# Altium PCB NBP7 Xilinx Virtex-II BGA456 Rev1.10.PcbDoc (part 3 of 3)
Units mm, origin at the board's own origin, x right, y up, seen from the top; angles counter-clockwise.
Board outline 69 x 80.99 mm, 6 copper layers (Top Layer, MidLayer1, InternalPlane1, InternalPlane2, MidLayer2, Bottom Layer); 101 components, 273 nets, 963 pads, 545 vias.
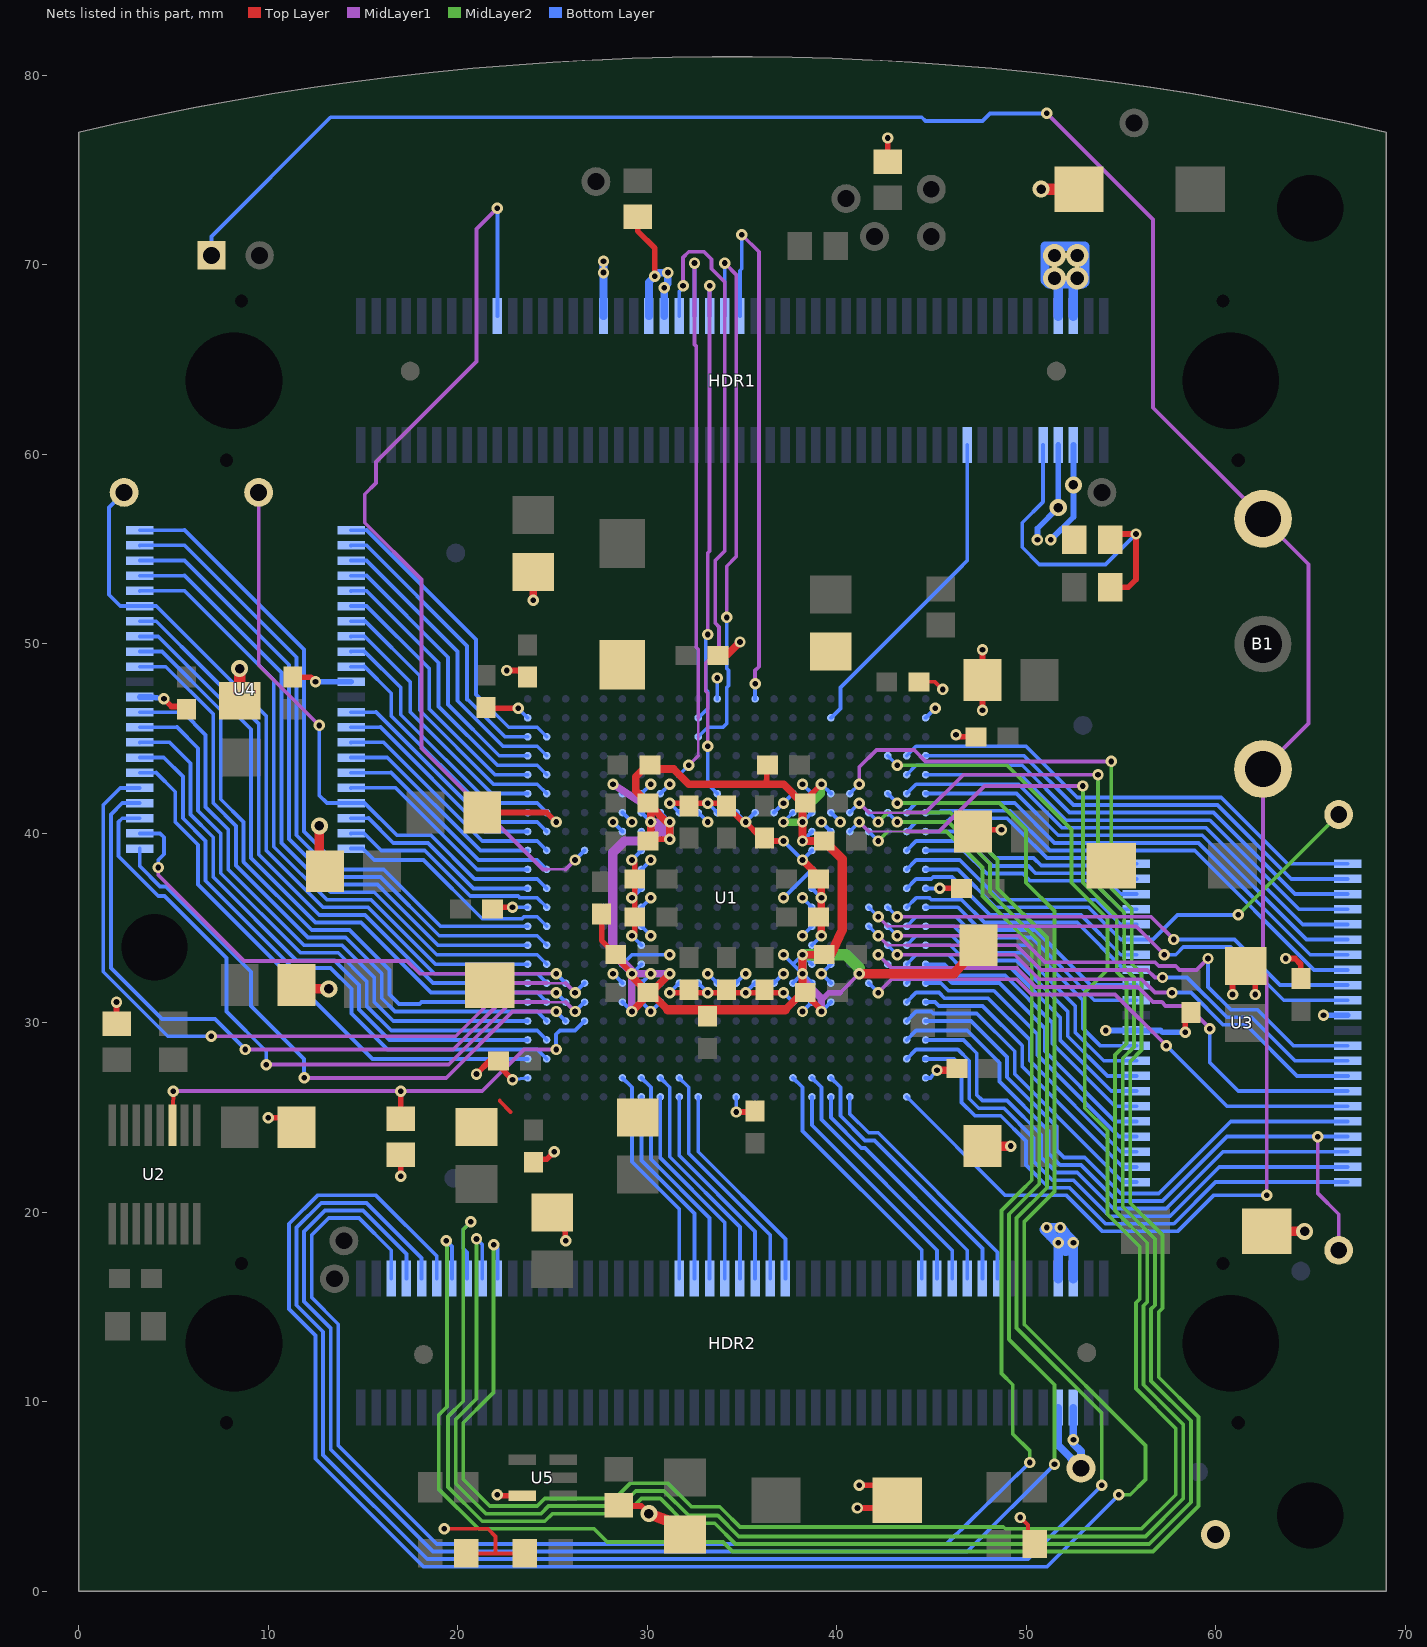
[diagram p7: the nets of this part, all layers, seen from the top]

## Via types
v1: diameter 0.6, hole 0.3, Top Layer to Bottom Layer, tented bottom, 520 vias
v2: diameter 0.9, hole 0.5, Top Layer to Bottom Layer, 17 vias
v3: diameter 1.2, hole 0.7, Top Layer to Bottom Layer, 8 vias

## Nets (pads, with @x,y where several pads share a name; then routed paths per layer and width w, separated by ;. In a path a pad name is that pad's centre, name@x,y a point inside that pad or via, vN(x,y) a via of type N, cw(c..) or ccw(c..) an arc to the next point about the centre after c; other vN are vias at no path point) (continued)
SP10: HDR2.86 U1.A18 | length 13.1
  Bottom Layer w0.2: U1.A18@40.7,26.1 40.7,25.2 41.7,24.2 42.2,24.2 48.5,17.9 HDR2.86@48.5,16.5
SP11: HDR2.84 U1.B17 | length 14.2
  Bottom Layer w0.2: U1.B17@39.7,27.1 40.2,26.6 40.2,25.1 41.5,23.8 42,23.8 47.7,18.1 HDR2.84@47.7,16.5
SP12: HDR2.82 U1.A17 | length 12.7
  Bottom Layer w0.2: U1.A17@39.7,26.1 39.7,25 41.3,23.4 41.5,23.4 46.9,18 HDR2.82@46.9,16.5
SP13: HDR2.80 U1.B16 | length 13.7
  Bottom Layer w0.2: U1.B16@38.7,27.1 39.2,26.6 39.2,24.9 46.1,18 HDR2.80@46.1,16.5
SP14: HDR2.78 U1.A16 | length 12.3
  Bottom Layer w0.2: U1.A16@38.7,26.1 38.7,24.6 45.3,18 HDR2.78@45.3,16.5
SP15: HDR2.76 U1.B15 | length 13.4
  Bottom Layer w0.2: U1.B15@37.7,27.1 38.2,26.6 38.2,24.3 44.5,18 HDR2.76@44.5,16.5
SPI_CLK: HDR1.46 U1.V9 | length 30.3
  MidLayer1 w0.127: 32.7,44.1 32.7,46.1
  MidLayer1 w0.2: v1(32.2,43.6) 32.7,44.1 ; v1(32.5,70.1) 32.5,65.8 32.6,65.7 32.6,49.8 32.7,49.7 32.7,46.1
  Bottom Layer w0.2: U1.V9@31.7,43.1 v1(32.2,43.6) ; HDR1.46@32.5,67.3 v1(32.5,70.1)
SPI_DIN: HDR1.44 U1.U11 | length 34.3
  MidLayer1 w0.2: v1(31.9,68.9) 31.9,70.4 32.2,70.7 33,70.7 33.4,70.3 33.4,69.8 34.1,69.1 34.1,54.9 33.6,54.4 33.6,51.1 33.8,50.9 33.8,49.7 33.1,49 33.1,47.5 33.2,47.4 v1(33.2,44.6)
  Bottom Layer w0.2: HDR1.44@31.7,67.3 31.7,68.6 31.9,68.8 v1(31.9,68.9) ; v1(33.2,44.6) 33.2,42.6 U1.U11@33.7,42.1
SPI_DOUT: HDR1.50 U1.Y10 | length 29.8
  MidLayer1 w0.2: v1(34.2,51.4) 34.2,54.1 34.7,54.6 34.7,69.5 v1@34.15,70.05 ; v1(34.1,70.1) v1@34.15,70.05 ; v1(34.1,70.1) 34.2,70.1 v1@34.15,70.05 ; v1(34.1,70.1) 34.1,70 v1@34.15,70.05
  Bottom Layer w0.2: U1.Y10@32.7,45.1 33.2,45.6 34,45.6 34.2,45.8 34.2,47.7 34.3,47.8 34.3,48.6 34.2,48.7 v1(34.2,51.4) ; HDR1.50@34.1,67.3 v1(34.1,70.1)
SPI_MODE: HDR1.52 U1.AB13 | length 29.4
  MidLayer1 w0.2: v1@34.9,71.6 34.95,71.65 v1(35,71.6) 35.9,70.7 35.9,48.8 35.7,48.6 v1(35.7,47.9)
  Bottom Layer w0.2: HDR1.52@34.9,67.3 34.9,69.7 35,69.8 v1(35,71.6) ; U1.AB13@35.7,47.1 v1(35.7,47.9)
SPI_SEL: HDR1.48 U1.AA10 | length 24.8
  MidLayer1 w0.2: v1(33.2,50.5) 33.2,54.8 33.3,54.9 v1(33.3,68.9)
  Bottom Layer w0.2: U1.AA10@32.7,46.1 33.2,46.6 33.2,47.5 33.1,47.6 33.1,50.5 v1(33.2,50.5) ; HDR1.48@33.3,67.3 v1(33.3,68.9)
SRAM0_A0: U1.G21 U3.5 | length 16.3
  Bottom Layer w0.2: U1.G21@43.7,32.1 44.2,32.6 45.6,32.6 46.1,32.1 48.6,32.1 51,29.7 51,28.5 54.7,24.8 U3.5@55.825,24.8
SRAM0_A1: U1.G22 U3.4 | length 15.1
  Bottom Layer w0.2: U1.G22@44.7,32.1 45.5,32.1 45.9,31.7 48.3,31.7 50.6,29.4 50.6,28.3 54.9,24 U3.4@55.825,24
SRAM0_A2: U1.F21 U3.3 | length 16.5
  Bottom Layer w0.2: U1.F21@43.7,31.1 44.2,31.6 45.4,31.6 45.7,31.3 48,31.3 50.2,29.1 50.2,28 55,23.2 U3.3@55.825,23.2
SRAM0_A3: U1.F22 U3.2 | length 15.4
  Bottom Layer w0.2: U1.F22@44.7,31.1 45.2,31.1 45.4,30.9 47.7,30.9 49.8,28.8 49.8,27.7 55.1,22.4 U3.2@55.825,22.4
SRAM0_A4: U1.E21 U3.1 | length 16.8
  Bottom Layer w0.2: U1.E21@43.7,30.1 44.2,30.6 45,30.6 45.1,30.5 47.4,30.5 49.4,28.5 49.4,27.3 55.1,21.6 U3.1@55.825,21.6
SRAM0_A5: U1.C22 U3.44 | length 28.7
  Bottom Layer w0.2: U1.C22@44.6,28.1 U1.C22@44.7,28.1 46.2,28.1 46.6,27.7 46.6,25.8 47.3,25.1 48.669,25.1 50,23.769 50,22.5 51.2,21.3 52.3,21.3 54.2,19.4 57.8,19.4 60,21.6 U3.44@66.975,21.6
SRAM0_A6: U1.C21 U3.43 | length 30.1
  Bottom Layer w0.2: U1.C21@43.7,28.1 44.2,28.6 46.4,28.6 47,28 47,26 47.5,25.5 48.834,25.5 50.4,23.934 50.4,22.7 51.4,21.7 52.5,21.7 54.4,19.8 57.6,19.8 60.2,22.4 U3.43@66.975,22.4
SRAM0_A7: U1.D22 U3.42 | length 29.2
  Bottom Layer w0.2: U1.D22@44.7,29.1 46.7,29.1 47.4,28.4 47.4,26.2 47.7,25.9 49,25.9 50.8,24.1 50.8,22.9 51.6,22.1 52.7,22.1 54.6,20.2 57.4,20.2 60.4,23.2 U3.42@66.975,23.2
SRAM0_A8: U1.N21 U3.18 | length 13.7
  Bottom Layer w0.2: U1.N21@43.7,38.1 44.2,38.6 46.5,38.6 48.6,36.5 53.7,36.5 55,35.2 U3.18@55.825,35.2
SRAM0_A9: U1.U21 U3.27 | length 26.5
  Bottom Layer w0.2: U1.U21@43.7,42.1 44.2,42.6 49.6,42.6 51.9,40.3 59.5,40.3 64.6,35.2 U3.27@66.975,35.2
SRAM0_A10: U1.V22 U3.26 | length 25.2
  Bottom Layer w0.2: U1.V22@44.7,43.1 49.7,43.1 52.1,40.7 59.7,40.7 64.4,36 U3.26@66.975,36
SRAM0_A11: U1.V21 U3.25 | length 26.3
  Bottom Layer w0.2: U1.V21@43.7,43.1 44.2,43.6 49.8,43.6 52.3,41.1 59.9,41.1 64.2,36.8 U3.25@66.975,36.8
SRAM0_A12: U1.W22 U3.24 | length 25
  Bottom Layer w0.2: U1.W22@44.7,44.1 49.9,44.1 52.5,41.5 60.1,41.5 64,37.6 U3.24@66.975,37.6
SRAM0_A13: U1.W21 U3.23 | length 26.1
  Bottom Layer w0.2: U1.W21@43.7,44.1 44.2,44.6 50,44.6 52.7,41.9 60.3,41.9 63.8,38.4 U3.23@66.975,38.4
SRAM0_A14: U1.R21 U3.22 | length 13.4
  Bottom Layer w0.2: U1.R21@43.7,40.1 44.2,40.6 ; 44.2,40.6 45.8,40.6 46,40.8 49,40.8 49.693,40.107 51.1,38.7 54.7,38.7 55,38.4 U3.22@55.825,38.4
SRAM0_A15: U1.R22 U3.21 | length 12.2
  Bottom Layer w0.2: U1.R22@44.7,40.1 47,40.1 48.4,38.7 50.4,38.7 50.8,38.3 54.3,38.3 55,37.6 U3.21@55.825,37.6
SRAM0_A16: U1.P21 U3.20 | length 13.5
  Bottom Layer w0.2: U1.P21@43.7,39.1 44.2,39.6 46.9,39.6 48.222,38.278 50.122,38.278 50.5,37.9 53.9,37.9 55,36.8 U3.20@55.825,36.8
SRAM0_A17: U1.P22 U3.19 | length 12.4
  Bottom Layer w0.2: U1.P22@44.7,39.1 46.7,39.1 47.922,37.878 49.822,37.878 50.2,37.5 53.5,37.5 55,36 U3.19@55.825,36
SRAM0_A18: U1.U22 U3.28 | length 25.5
  Bottom Layer w0.2: U1.U22@44.7,42.1 49.5,42.1 51.7,39.9 59.3,39.9 64.8,34.4 U3.28@66.975,34.4
SRAM0_D0: U1.H21 U3.7 | length 16
  Bottom Layer w0.2: U1.H21@43.7,33.1 44.2,33.6 45.9,33.6 46.6,32.9 49.2,32.9 51.8,30.3 51.8,29.1 54.5,26.4 U3.7@55.825,26.4
SRAM0_D1: U1.J22 U3.8 | length 14.7
  Bottom Layer w0.2: U1.J22@44.7,34.1 46,34.1 46.8,33.3 49.5,33.3 52.2,30.6 52.2,29.3 54.3,27.2 U3.8@55.825,27.2
SRAM0_D2: U1.J21 U3.9 | length 15.9
  Bottom Layer w0.2: U1.J21@43.7,34.1 44.2,34.6 46.1,34.6 47,33.7 49.8,33.7 52.6,30.9 52.6,29.5 54.1,28 U3.9@55.825,28
SRAM0_D3: U1.K22 U3.10 | length 14.6
  Bottom Layer w0.2: U1.K22@44.7,35.1 45.2,35.1 46.2,35.1 47.2,34.1 50.1,34.1 53,31.2 53,29.7 53.9,28.8 U3.10@55.825,28.8
SRAM0_D4: U1.K21 U3.13 | length 14.2
  Bottom Layer w0.2: U1.K21@43.7,35.1 44.2,35.6 46.3,35.6 47.4,34.5 50.3,34.5 53.6,31.2 U3.13@55.825,31.2
SRAM0_D5: U1.L22 U3.14 | length 12.8
  Bottom Layer w0.2: U1.L22@44.7,36.1 46.4,36.1 47.6,34.9 50.5,34.9 53.4,32 U3.14@55.825,32
SRAM0_D6: U1.L21 U3.15 | length 13.9
  Bottom Layer w0.2: U1.L21@43.7,36.1 44.2,36.6 44.9,36.6 45,36.5 46.6,36.5 47.8,35.3 52.7,35.3 55.2,32.8 U3.15@55.825,32.8
SRAM0_D7: U1.M21 U3.16 | length 14.1
  Bottom Layer w0.2: U1.M21@43.7,37.1 44.2,37.6 45,37.6 45.1,37.7 46.1,37.7 48.1,35.7 52.9,35.7 55,33.6 U3.16@55.825,33.6
SRAM0_D8: U1.T21 U3.29 | length 26.8
  Bottom Layer w0.2: U1.T21@43.7,41.1 44.2,41.6 49.4,41.6 51.5,39.5 59.1,39.5 65,33.6 U3.29@66.975,33.6
SRAM0_D9: U1.T22 U3.30 | length 25.8
  Bottom Layer w0.2: U1.T22@44.7,41.1 45.4,41.1 45.5,41.2 49.166,41.2 51.266,39.1 58.9,39.1 65.2,32.8 U3.30@66.975,32.8
SRAM0_D10: U1.L20 U3.31 | length 26
  MidLayer1 w0.2: v1(43.2,35.6) 56.6,35.6 v1(57.8,34.4)
  Bottom Layer w0.2: U1.L20@42.7,36.1 v1(43.2,35.6) ; v1(57.8,34.4) 61,34.4 63.4,32 U3.31@66.975,32
SRAM0_D11: U1.L19 U3.32 | length 27.6
  MidLayer1 w0.127: 42.7,35.1 43.7,35.1
  MidLayer1 w0.2: v1(42.2,35.6) 42.7,35.1 ; 43.7,35.1 55.8,35.1 v1(57.3,33.6)
  Bottom Layer w0.2: U1.L19@41.7,36.1 v1(42.2,35.6) ; v1(57.3,33.6) 57.9,33.6 58.3,34 60.8,34 63.6,31.2 U3.32@66.975,31.2
SRAM0_D12: U1.K20 U3.35 | length 28.3
  MidLayer1 w0.2: v1(43.2,34.6) 49.6,34.6 51,33.2 56.8,33.2 57,33 57.9,33 58.1,32.8 59,32.8 v1(59.6,33.4)
  Bottom Layer w0.2: U1.K20@42.7,35.1 v1(43.2,34.6) ; v1(59.6,33.4) 59.6,31.9 60.8,30.7 62.2,30.7 64.1,28.8 U3.35@66.975,28.8
SRAM0_D13: U1.K19 U3.36 | length 28.2
  MidLayer1 w0.127: 42.7,34.1 43.7,34.1
  MidLayer1 w0.2: v1(42.2,34.6) 42.7,34.1 ; 43.7,34.1 49.5,34.1 50.8,32.8 56.4,32.8 56.8,32.4 v1(57.2,32.4)
  Bottom Layer w0.2: U1.K19@41.7,35.1 v1(42.2,34.6) ; v1(57.2,32.4) 58.5,32.4 60.6,30.3 61.9,30.3 64.2,28 U3.36@66.975,28
SRAM0_D14: U1.J20 U3.37 | length 27.2
  MidLayer1 w0.2: v1(43.2,33.6) 49.4,33.6 50.7,32.3 56.1,32.3 56.8,31.6 v1(57.7,31.6)
  Bottom Layer w0.2: U1.J20@42.7,34.1 v1(43.2,33.6) ; v1(57.7,31.6) 58.7,31.6 60.4,29.9 61.6,29.9 64.3,27.2 U3.37@66.975,27.2 U3.37@67,27.2
SRAM0_D15: U1.H20 U3.38 | length 29.6
  MidLayer1 w0.2: v1(42.2,33.6) 42.9,32.9 49.5,32.9 ; 49.534,32.9 49.5,32.9 ; v1(59.7,29.7) 58.5,30.9 57.367,30.9 57.167,31.1 56.7,31.1 55.9,31.9 50.5,31.9 49.5,32.9
  Bottom Layer w0.2: v1(42.2,33.6) U1.H20@42.7,33.1 ; v1(59.7,29.7) 59.7,27.9 61.2,26.4 U3.38@66.975,26.4
SRAM0_E: U1.H22 U3.6 | length 14.9
  Bottom Layer w0.2: U1.H22@44.7,33.1 45.7,33.1 46.3,32.5 48.9,32.5 51.4,30 51.4,28.9 54.7,25.6 U3.6@55.825,25.6
SRAM0_LB: U1.G19 U3.39 | length 28.5
  MidLayer1 w0.2: v1(42.2,31.6) 42.9,32.3 49.5,32.3 50.3,31.5 54.7,31.5 v1(57.4,28.8)
  Bottom Layer w0.2: U1.G19@41.7,32.1 v1(42.2,31.6) ; v1(57.4,28.8) 58.4,27.8 60.6,25.6 U3.39@66.975,25.6
SRAM0_OE: TP13.1 U1.D21 U3.41 | length 36.4
  MidLayer1 w0.2: v1(65.4,24) 65.4,21 66.5,19.9 TP13.1@66.5,18
  Bottom Layer w0.2: U1.D21@43.7,29.1 44.2,29.6 46.9,29.6 48.6,27.9 48.6,26.9 51.2,24.3 51.2,23.1 51.8,22.5 52.9,22.5 54.8,20.6 57.2,20.6 60.6,24 v1(65.4,24) U3.41@66.975,24
SRAM0_UB: U1.E22 U3.40 | length 29
  Bottom Layer w0.2: U1.E22@44.7,30.1 47.1,30.1 49,28.2 49,27.134 51.6,24.534 51.6,23.3 52,22.9 53.1,22.9 55,21 57,21 60.8,24.8 U3.40@66.975,24.8
SRAM0_W: TP15.1 U1.N22 U3.17 | length 26.1
  MidLayer2 w0.2: v1(61.2,35.7) TP15.1@66.5,41
  Bottom Layer w0.2: U1.N22@44.7,38.1 46.4,38.1 48.4,36.1 53.3,36.1 55,34.4 U3.17@55.825,34.4 56.7,34.4 58,35.7 v1(61.2,35.7)
SRAM1_A0: U1.G4 U4.5 | length 39.5
  MidLayer1 w0.127: 24.7,32.1 25.7,32.1
  MidLayer1 w0.2: v1(7,29.3) 19.903,29.3 22.703,32.1 24.7,32.1 ; 25.7,32.1 v1(26.2,31.6)
  Bottom Layer w0.2: U4.5@3.225,42.4 2.2,42.4 1.3,41.5 1.3,32.7 4.2,29.8 4.7,29.3 v1(7,29.3) ; v1(26.2,31.6) U1.G4@26.7,32.1
SRAM1_A1: U1.F3 U4.4 | length 37.1
  MidLayer1 w0.2: v1(8.8,28.6) 19.769,28.6 22.769,31.6 v1(25.2,31.6)
  Bottom Layer w0.2: U4.4@3.225,41.6 2.3,41.6 1.7,41 1.7,32.9 4.4,30.2 7.2,30.2 v1(8.8,28.6) ; v1(25.2,31.6) U1.F3@25.7,31.1
SRAM1_A2: U1.F4 U4.3 | length 36
  MidLayer1 w0.127: 24.7,31.1 25.7,31.1
  MidLayer1 w0.2: v1(9.9,27.8) 19.534,27.8 22.834,31.1 24.7,31.1 ; 25.7,31.1 v1(26.2,30.6)
  Bottom Layer w0.2: U4.3@3.225,40.8 2.3,40.8 2.1,40.6 2.1,38.8 4.2,36.7 4.534,36.7 7.8,33.434 7.8,30.6 9.9,28.5 v1(9.9,27.8) ; v1(26.2,30.6) U1.F4@26.7,31.1
SRAM1_A3: U1.G3 U4.2 | length 27.3
  MidLayer1 w0.2: v1(4.2,38.2) 4.2,37.8 8.731,33.269 17.331,33.269 18,32.6 v1(25.2,32.6)
  Bottom Layer w0.2: U4.2@3.225,40 4.3,40 4.5,39.8 4.5,38.9 4.2,38.6 v1(4.2,38.2) ; v1(25.2,32.6) U1.G3@25.7,32.1
SRAM1_A4: U1.E3 U4.1 | length 31.3
  MidLayer1 w0.2: v1(11.9,27.1) 19.4,27.1 22.9,30.6 v1(25.2,30.6)
  Bottom Layer w0.2: U4.1@3.225,39.2 3.225,38.275 4.3,37.2 4.6,37.2 9.1,32.7 9.1,30.9 11.9,28.1 v1(11.9,27.1) ; v1(25.2,30.6) U1.E3@25.7,30.1
SRAM1_A5: U1.K2 U4.44 | length 12.1
  Bottom Layer w0.2: U4.44@14.375,39.2 14.99,39.21 15.6,38.6 18.203,38.6 21.303,35.5 23.4,35.5 23.5,35.6 24.2,35.6 U1.K2@24.7,35.1
SRAM1_A6: U1.L2 U4.43 | length 11.9
  Bottom Layer w0.2: U4.43@14.375,40 15.059,40.01 15.969,39.1 18.269,39.1 20.669,36.7 23.2,36.7 23.3,36.6 24.2,36.6 U1.L2@24.7,36.1
SRAM1_A7: U1.M1 U4.42 | length 10.9
  Bottom Layer w0.2: U4.42@14.375,40.8 15.29,40.81 16.6,39.5 18.434,39.5 20.834,37.1 U1.M1@23.7,37.1
SRAM1_A8: U1.H1 U4.18 | length 33.8
  Bottom Layer w0.2: U4.18@3.225,52.8 5.59,52.81 10.3,48.1 10.3,39.3 13.1,36.5 15.437,36.5 18.837,33.1 U1.H1@23.7,33.1
SRAM1_A9: U1.V2 U4.27 | length 15.7
  Bottom Layer w0.2: U4.27@14.375,52.8 15.19,52.81 18.996,49.004 18.996,46.704 22.1,43.6 24.2,43.6 U1.V2@24.7,43.1
SRAM1_A10: U1.W1 U4.26 | length 14.7
  Bottom Layer w0.2: U4.26@14.375,53.6 15.19,53.61 19.5,49.3 19.5,46.8 22.2,44.1 U1.W1@23.7,44.1
SRAM1_A11: U1.W2 U4.25 | length 16.1
  Bottom Layer w0.2: U4.25@14.375,54.4 15.19,54.41 20,49.6 20,47 22.4,44.6 24.2,44.6 U1.W2@24.7,44.1
SRAM1_A12: U1.Y1 U4.24 | length 15.2
  Bottom Layer w0.2: U4.24@14.375,55.2 15.19,55.21 20.5,49.9 20.5,47.1 ; 20.5,47.066 20.5,47.1 ; U1.Y1@23.7,45.1 22.5,45.1 20.517,47.083 20.5,47.1
SRAM1_A13: U1.Y2 U4.23 | length 16.5
  Bottom Layer w0.2: U4.23@14.375,56 15.19,56.01 20.968,50.232 20.968,47.332 22.7,45.6 24.2,45.6 U1.Y2@24.7,45.1
SRAM1_A14: U1.K1 U4.22 | length 34.8
  Bottom Layer w0.2: U4.22@3.225,56 5.59,56.01 6.2,55.4 11.9,49.7 11.9,40.1 13.9,38.1 16.1,38.1 19.1,35.1 U1.K1@23.7,35.1
SRAM1_A15: U1.J2 U4.21 | length 35.7
  Bottom Layer w0.2: U4.21@3.225,55.2 5.59,55.21 6.2,54.6 11.5,49.3 11.5,39.9 13.7,37.7 15.934,37.7 19.034,34.6 24.2,34.6 U1.J2@24.7,34.1
SRAM1_A16: U1.J1 U4.20 | length 34.3
  Bottom Layer w0.2: U4.20@3.225,54.4 5.59,54.41 6.2,53.8 11.1,48.9 11.1,39.7 13.5,37.3 15.769,37.3 16.369,36.7 18.969,34.1 U1.J1@23.7,34.1
SRAM1_A17: U1.H2 U4.19 | length 35.2
  Bottom Layer w0.2: U4.19@3.225,53.6 5.59,53.61 10.7,48.5 10.7,39.5 13.3,36.9 15.603,36.9 18.903,33.6 24.2,33.6 U1.H2@24.7,33.1
SRAM1_A18: U1.V1 U4.28 | length 14.3
  Bottom Layer w0.2: U4.28@14.375,52 15.19,52.01 18.5,48.7 18.5,46.566 21.966,43.1 U1.V1@23.7,43.1
SRAM1_D0: U1.C2 U4.7 | length 31.3
  Bottom Layer w0.2: U4.7@3.225,44 4.49,44.01 5.5,43 5.5,40.8 6.7,39.6 6.7,37.5 11.3,32.9 13.3,32.9 14.4,31.8 14.4,30.5 16.3,28.6 24.2,28.6 U1.C2@24.7,28.1
SRAM1_D1: U1.D1 U4.8 | length 30.6
  Bottom Layer w0.2: U4.8@3.225,44.8 4.79,44.81 5.9,43.7 5.9,41 7.1,39.8 7.1,37.7 11.5,33.3 13.5,33.3 14.8,32 14.8,30.7 16.4,29.1 U1.D1@23.7,29.1
SRAM1_D2: U1.D2 U4.9 | length 32.2
  Bottom Layer w0.2: U4.9@3.225,45.6 5.19,45.61 6.3,44.5 6.3,41.2 7.5,40 7.5,37.9 11.7,33.7 13.7,33.7 15.2,32.2 15.2,30.9 16.5,29.6 24.2,29.6 U1.D2@24.7,29.1
SRAM1_D3: U1.E1 U4.10 | length 31.4
  Bottom Layer w0.2: U4.10@3.225,46.4 5.5,46.4 6.7,45.2 6.7,41.4 7.9,40.2 7.9,38.1 11.9,34.1 13.9,34.1 15.6,32.4 15.6,31.1 16.6,30.1 U1.E1@23.7,30.1
SRAM1_D4: U1.E2 U4.13 | length 34
  Bottom Layer w0.2: U4.13@3.225,48.8 4.6,48.8 7.1,46.3 7.1,41.6 8.3,40.4 8.3,38.3 12.1,34.5 14.1,34.5 16,32.6 16,31.3 16.7,30.6 24.2,30.6 U1.E2@24.7,30.1
SRAM1_D5: U1.F1 U4.14 | length 33
  Bottom Layer w0.2: U4.14@3.225,49.6 4.4,49.6 7.5,46.5 7.5,41.8 8.7,40.6 8.7,38.5 12.3,34.9 14.3,34.9 16.4,32.8 16.4,31.5 16.9,31 18,31 18.1,31.1 U1.F1@23.7,31.1
SRAM1_D6: U1.F2 U4.15 | length 33.5
  Bottom Layer w0.2: U4.15@3.225,50.4 4.2,50.4 9.1,45.5 9.1,38.7 12.5,35.3 14.9,35.3 18.6,31.6 24.2,31.6 U1.F2@24.7,31.1
SRAM1_D7: U1.G1 U4.16 | length 32.4
  Bottom Layer w0.2: U4.16@3.225,51.2 4.1,51.2 6.7,48.6 9.5,45.8 9.5,38.9 12.7,35.7 15.106,35.7 18.706,32.1 U1.G1@23.7,32.1
SRAM1_D8: U1.U2 U4.29 | length 15.2
  Bottom Layer w0.2: U4.29@14.375,51.2 15.11,51.21 18,48.32 18,46.5 21.9,42.6 24.2,42.6 U1.U2@24.7,42.1
SRAM1_D9: U1.U1 U4.30 | length 13.7
  Bottom Layer w0.2: U4.30@14.375,50.4 15.09,50.41 17.5,48 17.5,46.4 21.8,42.1 U1.U1@23.7,42.1
SRAM1_D10: U1.T2 U4.31 | length 14.7
  Bottom Layer w0.2: U4.31@14.375,49.6 15.09,49.61 17,47.7 17,46.266 21.666,41.6 24.2,41.6 U1.T2@24.7,41.1
SRAM1_D11: U1.T1 U4.32 | length 13.2
  Bottom Layer w0.2: U4.32@14.375,48.8 15.09,48.81 16.5,47.4 16.5,46.2 21.6,41.1 U1.T1@23.7,41.1
SRAM1_D12: U1.R2 U4.35 | length 12.9
  Bottom Layer w0.2: U4.35@14.375,46.4 15.69,46.41 21.5,40.6 24.2,40.6 U1.R2@24.7,40.1
SRAM1_D13: U1.R1 U4.36 | length 11.6
  Bottom Layer w0.2: U4.36@14.375,45.6 15.925,45.61 21.434,40.1 U1.R1@23.7,40.1
SRAM1_D14: U1.P2 U4.37 | length 12.7
  Bottom Layer w0.2: U4.37@14.375,44.8 16.09,44.81 21.3,39.6 24.2,39.6 U1.P2@24.7,39.1
SRAM1_D15: U1.P1 U4.38 | length 11.4
  Bottom Layer w0.2: U4.38@14.375,44 16.29,44.01 21.2,39.1 U1.P1@23.7,39.1
SRAM1_E: U1.C1 U4.6 | length 28.9
  Bottom Layer w0.2: U4.6@3.225,43.2 4.09,43.21 5.1,42.2 5.1,40.6 6.3,39.4 6.3,37.3 15.5,28.1 U1.C1@23.7,28.1
SRAM1_LB: U1.N2 U4.39 | length 12.4
  Bottom Layer w0.2: U4.39@14.375,43.2 16.49,43.21 21.1,38.6 24.2,38.6 U1.N2@24.7,38.1
SRAM1_OE: TP14.1 U1.M2 U4.41 | length 31.4
  MidLayer1 w0.2: TP14.1@9.5,58 9.5,48.9 v1(12.7,45.7)
  Bottom Layer w0.2: v1(12.7,45.7) 12.7,42 13.1,41.6 U4.41@14.375,41.6 15.09,41.61 16.8,39.9 18.6,39.9 20.9,37.6 24.2,37.6 U1.M2@24.7,37.1
SRAM1_UB: U1.N1 U4.40 | length 11.1
  Bottom Layer w0.2: U4.40@14.375,42.4 16.725,42.41 21.034,38.1 U1.N1@23.7,38.1
SRAM1_W: TP12.1 U1.G2 U4.17 | length 41.5
  Bottom Layer w0.2: TP12.1@2.4,58 1.6,57.2 1.6,52.6 2.2,52 U4.17@3.225,52 4.1,52 9.9,46.2 9.9,39.1 12.9,36.1 15.272,36.1 15.972,35.4 18.772,32.6 24.2,32.6 U1.G2@24.7,32.1
SW0: HDR2.44 U1.B6 | length 11.8
  Bottom Layer w0.2: U1.B6@28.7,27.1 29.2,26.6 29.2,22.672 31.7,20.172 HDR2.44@31.7,16.5
SW1: HDR2.46 U1.A7 | length 10.8
  Bottom Layer w0.2: U1.A7@29.7,26.1 29.7,22.737 32.5,19.937 HDR2.46@32.5,16.5
SW2: HDR2.48 U1.B7 | length 12.1
  Bottom Layer w0.2: U1.B7@29.7,27.1 30.2,26.6 30.2,22.803 33.3,19.703 HDR2.48@33.3,16.5
SW3: HDR2.50 U1.A8 | length 11
  Bottom Layer w0.2: U1.A8@30.7,26.1 30.7,22.869 34.1,19.469 HDR2.50@34.1,16.5
SW4: HDR2.52 U1.B8 | length 12.3
  Bottom Layer w0.2: U1.B8@30.7,27.1 31.2,26.6 31.2,22.934 34.9,19.234 HDR2.52@34.9,16.5
SW5: HDR2.54 U1.A9 | length 11.3
  Bottom Layer w0.2: U1.A9@31.7,26.1 31.7,23 35.7,19 HDR2.54@35.7,16.5
SW6: HDR2.56 U1.B9 | length 12.6
  Bottom Layer w0.2: U1.B9@31.7,27.1 32.2,26.6 32.2,23.1 36.5,18.8 HDR2.56@36.5,16.5
SW7: HDR2.58 U1.A10 | length 11.5
  Bottom Layer w0.2: U1.A10@32.7,26.1 32.7,23.2 37.3,18.6 HDR2.58@37.3,16.5
SWC0: HDR2.18 U1.R18 | length 111.1
  MidLayer1 w0.127: 41.7,40.1 43.7,40.1
  MidLayer1 w0.2: v1(41.2,40.6) 41.7,40.1 ; 43.7,40.1 45.4,40.1 47.8,42.5 v1(53,42.5)
  MidLayer2 w0.2: v1(21,18.6) 21,10.166 19.9,9.066 19.9,5.7 21.5,4.1 24.4,4.1 24.8,4.5 28.6,4.5 29.4,5.3 30.9,5.3 32.2,4 33.734,4 34.834,2.9 56.3,2.9 58.3,4.9 58.3,8.8 56.2,10.9 56.2,15.069 56.4,15.269 56.4,18.4 54.7,20.1 54.7,24.5 54.7,28.3 55.3,28.9 55.3,32.2 54.781,32.719 54.781,35.619 53,37.4 v1(53,42.5)
  Bottom Layer w0.2: v1(21,18.6) 21.3,18.3 HDR2.18@21.3,16.5 ; U1.R18@40.7,40.1 v1(41.2,40.6)
SWC1: HDR2.16 U1.T18 | length 115.5
  MidLayer1 w0.127: 41.7,41.1 43.7,41.1
  MidLayer1 w0.2: v1(41.2,41.6) 41.7,41.1 ; 43.7,41.1 44.7,41.1 46.7,43.1 v1(53.8,43.1)
  MidLayer2 w0.2: v1(20.7,19.5) 20.3,19.1 20.3,10.031 19.5,9.231 19.5,5.5 21.3,3.7 24.6,3.7 25,4.1 28.9,4.1 29.7,4.9 30.7,4.9 32.005,3.595 33.574,3.595 34.669,2.5 56.5,2.5 58.7,4.7 58.7,9 56.6,11.1 56.6,14.903 56.8,15.103 56.8,18.6 55.1,20.3 55.1,28.134 55.7,28.734 55.7,32.4 55.181,32.919 55.181,35.819 53.8,37.2 v1(53.8,43.1)
  Bottom Layer w0.2: HDR2.16@20.5,16.5 20.5,17.9 20.3,18.1 20.3,19.1 v1(20.7,19.5) ; U1.T18@40.7,41.1 v1(41.2,41.6)
SWC2: HDR2.14 U1.U18 | length 115.3
  MidLayer1 w0.2: v1(41.2,42.6) 41.2,43.5 42.1,44.4 44.1,44.4 44.7,43.8 v1(54.5,43.8)
  MidLayer2 w0.2: v1(19.4,18.5) 19.446,18.454 19.446,9.743 19,9.297 19,5.4 21.1,3.3 27.2,3.3 27.9,2.6 34.003,2.6 34.503,2.1 56.7,2.1 59.1,4.5 59.1,9.2 57,11.3 57,14.737 57.2,14.937 57.2,18.8 55.5,20.5 55.5,27.969 56.1,28.569 56.1,32.6 55.581,33.119 55.581,36.019 54.5,37.1 v1(54.5,43.8)
  Bottom Layer w0.2: v1(19.4,18.5) 19.7,18.2 HDR2.14@19.7,16.5 ; U1.U18@40.7,42.1 v1(41.2,42.6)
SWC3: HDR2.6 U1.R19 | length 99.8
  MidLayer2 w0.127: 42.7,40.1 43.7,40.1
  MidLayer2 w0.2: v1(42.2,39.6) 42.7,40.1 ; 43.7,40.1 45.8,40.1 47.7,38.2 47.7,36.7 50.3,34.1 50.3,21.7 49.7,21.1 48.7,20.1 48.7,11.5 49.3,10.9 49.3,8.3 50.2,7.4 v1(50.2,6.8)
  Bottom Layer w0.2: HDR2.6@16.5,16.5 16.5,18 14.8,19.7 13.2,19.7 12.3,18.8 12.3,15.5 13.7,14.1 13.7,7.7 18.9,2.5 45.8,2.5 v1(50.2,6.8) ; U1.R19@41.7,40.1 v1(42.2,39.6)
SWR0: HDR2.20 U1.W20 | length 105.2
  MidLayer2 w0.2: 21.599,10.199 20.3,8.9 20.3,5.9 21.7,4.5 24.2,4.5 24.6,4.9 28.3,4.9 29.1,5.7 31.1,5.7 32.336,4.464 33.836,4.464 33.993,4.307 34.9,3.4 48.8,3.4 48.9,3.3 56.1,3.3 57.9,5.1 57.9,8.6 55.8,10.7 55.8,15.234 56,15.434 56,18.2 54.3,19.9 54.3,24.3 54.211,24.389 53.1,25.5 53.1,31.603 54.3,32.803 54.3,35.5 52.4,37.4 52.4,40.2 49,43.6 v1(43.2,43.6) ; 21.6,10.197 21.9,10.497 v1(21.9,18.3)
  Bottom Layer w0.2: v1(21.9,18.3) 22.1,18.1 HDR2.20@22.1,16.5 ; U1.W20@42.7,44.1 v1(43.2,43.6)
SWR1: HDR2.12 U1.U20 | length 118.3
  MidLayer2 w0.2: v1(43.2,41.6) 48.6,41.6 50,40.2 50,37.4 51.5,35.9 51.5,21.1 49.9,19.5 49.9,14.066 49.934,14.066 56.3,7.7 56.3,5.9 55.5,5.1 v1(54.9,5.1)
  Bottom Layer w0.2: HDR2.12@18.9,16.5 18.9,17.7 15.7,20.9 12.6,20.9 11.1,19.4 11.1,14.9 12.5,13.5 12.5,7 18.2,1.3 51.1,1.3 v1(54.9,5.1) ; U1.U20@42.7,42.1 v1(43.2,41.6)
SWR2: HDR2.10 U1.T19 | length 111.9
  MidLayer2 w0.127: 42.7,41.1 43.7,41.1
  MidLayer2 w0.2: v1(42.2,40.6) 42.7,41.1 ; 43.7,41.1 46,41.1 48.5,38.6 48.5,37.1 51.1,34.5 51.1,21.3 49.5,19.7 49.5,13.9 54,9.4 v1(54,5.6)
  Bottom Layer w0.2: HDR2.10@18.1,16.5 18.1,17.6 15.2,20.5 12.8,20.5 11.5,19.2 11.5,15.1 12.9,13.7 12.9,7.2 18.4,1.7 50.1,1.7 v1(54,5.6) ; U1.T19@41.7,41.1 v1(42.2,40.6)
SWR3: HDR2.8 U1.T20 | length 103.5
  MidLayer2 w0.2: v1(43.2,40.6) 45.9,40.6 48.1,38.4 48.1,36.9 50.7,34.3 50.7,21.5 49.1,19.9 49.1,13.3 51.5,10.9 v1(51.5,6.7)
  Bottom Layer w0.2: HDR2.8@17.3,16.5 17.3,17.8 15,20.1 13,20.1 11.9,19 11.9,15.3 13.3,13.9 13.3,7.5 18.7,2.1 46.9,2.1 v1(51.5,6.7) ; U1.T20@42.7,41.1 v1(43.2,40.6)
TEMP_ALERT: R13.2 U1.E4 U2.11 | length 27
  Top Layer w0.2: U2.11@4.952,24.6 v1(5,26.4)
  Top Layer w0.3: R13.2@17,24.95 v1(17,26.4)
  MidLayer1 w0.2: v1(5,26.4) v1(17,26.4) 21.3,26.4 23.5,28.6 v1(25.2,28.6)
  Bottom Layer w0.2: v1(25.2,28.6) 25.2,29.4 25.4,29.6 26.2,29.6 U1.E4@26.7,30.1
TEST: HDR1.81 U1.AA17 | length 17.4
  Bottom Layer w0.2: U1.AA17@39.7,46.1 40.2,46.6 40.2,47.7 46.4,53.9 46.9,54.4 HDR1.81@46.9,60.5
VBATT: B1.0 B1.1 JP1.1 U1.A21 | length 134.6
  MidLayer1 w0.2: v1(51.1,78) 56.7,72.4 56.7,62.466 62.5,56.666 B1.1@62.5,56.604 64.9,54.204 64.9,45.796 B1.0@62.5,43.396 62.5,32.7 62.7,32.5 v1(62.7,20.9)
  Bottom Layer w0.2: JP1.1@7.012,70.507 7.012,71.512 13.3,77.8 44.5,77.8 44.7,77.6 47.7,77.6 48.1,78 v1(51.1,78) ; U1.A21@43.7,26.1 48.9,20.9 52.134,20.9 54.034,19 58,19 59.9,20.9 v1(62.7,20.9)
  Bottom Layer w0.3: JP1.1@7,70.519 JP1.1@7.012,70.507
VCC: C1.1 C2.1 C7.1 C8.1 C9.1 C10.1 C11.1 C12.1 C13.1 C14.1 C15.1 C16.1 C17.1 C18.1 C19.1 C20.1 C22.1 C23.1 C24.1 C25.1 C26.1 C27.1 C28.1 C29.1 C30.1 C31.1 C32.1 C33.1 C34.1 C35.1 C36.1 C37.1 C38.1 C39.1 C40.1 C41.1 C42.1 C52.1 C56.1 C57.1 C58.1 HDR1.34 HDR1.40 HDR1.42 HDR1.94 HDR1.96 HDR2.94 HDR2.96 R4.1 R5.2 R6.1 R7.2 R11.2 R12.2 R13.1 TP10.1 U1.A12 U1.AA1 U1.AA22 U1.AB11 U1.B1 U1.B22 U1.F7 U1.F8 U1.F15 U1.F16 U1.G6 U1.G9 U1.G10 U1.G11 U1.G12 U1.G13 U1.G14 U1.G17 U1.H6 U1.H17 U1.J7 U1.J16 U1.K7 U1.K16 U1.L1 U1.L7 U1.L16 U1.M7 U1.M16 U1.M22 U1.N7 U1.N16 U1.P7 U1.P16 U1.R6 U1.R17 U1.T6 U1.T9 U1.T10 U1.T11 U1.T12 U1.T13 U1.T14 U1.T17 U1.U7 U1.U8 U1.U15 U1.U16 U3.11 U3.33 U4.11 U4.33 U5.5 | length 171.4
  Top Layer w0.2: v1(19.3,3.3) 21.6,3.3 22,2.9 22,2 ; R12.2@20.45,2 22,2 ; R7.2@23.55,2 22,2 ; C22.1@44.35,48 45.2,48 v1(45.6,47.6) ; v1(49.7,3.9) 50.1,3.5 50.1,3.1 50.359,3.137 50.45,3.15 R11.2@50.45,2.5
  Top Layer w0.3: R4.1@2,30 v1(2,31.1) ; v1(4.5,47.1) 4.9,46.7 C41.1@5.6,46.7 ; v1(10,25) C9.1@11.5,25 ; C42.1@11.3,48.25 12.25,48.25 v1(12.5,48) ; v1(17,21.9) R13.1@17,23.05 ; v1(21,27.3) 21.7,28 C38.1@22.15,28 22.15,27.75 v1(22.9,27) ; C11.1@21.3,41.1 24.7,41.1 v1(25.2,40.6) ; C24.1@21.55,46.6 v1(23.2,46.6) ; C28.1@21.9,36.1 v1(22.9,36.1) ; v1(22.1,5.1) 22.159,5.041 U5.5@23.42,5.041 ; v1(22.6,48.6) 23.2,48.6 C23.1@23.6,48.2 ; C27.1@24,22.8 24.7,22.8 v1(25.1,23.2) ; C14.1@25.6,19.8 v1(25.7,18.5) ; C52.1@28.5,4.55 29.1,4.5 29.7,4.5 v2(30.1,4.1) ; v1@29.1,36.7 v1(29.2,36.6) ; v1(29.2,34.6) 29.35,34.75 C32.1@29.35,35.6 29.35,36.45 v1(29.2,36.6) ; v1(29.2,38.6) 29.35,38.45 C37.1@29.35,37.6 29.35,36.75 v1(29.2,36.6) ; R5.2@29.5,72.55 29.5,71.8 30.4,70.9 v1(30.4,69.4) ; v1(31.2,31.6) 32.2,31.6 v1(33.2,31.6) 34.2,31.6 v1(35.2,31.6) 36.2,31.6 v1(37.2,31.6) ; v1(31.2,41.6) 32.2,41.6 v1(33.2,41.6) 34.2,41.6 C25.1@34.3,41.6 ; C25.1@34.2,41.45 35.05,40.6 v1(35.2,40.6) ; v1(34.7,25.3) C17.1@35.7,25.3 ; v1(35.2,40.6) C19.1@36,39.8 ; C19.1@36.2,39.6 v1(37.2,39.6) ; v1(41.1,4.4) 42.4,4.4 C56.1@42.8,4.5 ; v1(41.2,5.6) C56.1@43.1,5.6 ; R6.1@42.7,75.45 v1(42.7,76.7) ; v1(45.45,37.1) C29.1@46.6,37.1 ; v1(46.3,45.2) 46.2,45.1 46.3,45.1 C34.1@47.35,45.1 ; C16.1@47.2,40.2 v1(48.7,40.2) ; v1(47.7,49.7) C13.1@47.7,48.1 v1(47.7,46.5) ; v1(58.4,29.5) 58.4,30.55 C33.1@58.7,30.55 ; v1(60.9,31.5) C2.1@60.9,32.5 ; v1(62.1,31.5) C2.1@62.1,32.7 ; v1(63.7,33.4) 64.2,33.4 64.5,33.1 C18.1@64.5,32.35 ; v1(47.7,46.5) 47.7,46.4 v1(47.7,46.5)
  Top Layer w0.4: v1(24,52.3) C12.1@24,53.8 ; C35.1@33.75,49.4 34.2,49.4 v1(34.9,50.1) ; v1(38.2,38.6) 39.125,37.675 39.2,37.6 v1(39.2,36.6) 39.2,35.6 v1(39.2,34.6) ; v1(45.3,27.5) C39.1@46.3,27.5
  Top Layer w0.5: C8.1@11.5,31.8 v2(13.2,31.8) ; v2(12.7,40.4) 12.7,38.6 12.926,37.991 C10.1@12.9,38 ; C15.1@47.8,23.5 v1(49.2,23.5) ; C57.1@62.7,19 v2(64.7,19)
  Top Layer w0.6: C7.1@8.5,47 v2(8.5,48.7) ; v2(30.1,4.1) 31.7,3.5 31.4,3.4 31.6,3.2 31.758,2.88 31.878,2.637 31.89,2.633 C1.1@32,2.6 ; v2(50.8,74) C58.1@52.8,74
  Bottom Layer w0.2: v1(22.9,27) U1.B1@23.7,27.1 ; v1(22.9,36.1) U1.L1@23.7,36.1 ; v1(23.2,46.6) U1.AA1@23.7,46.1 ; v1(28.2,32.6) U1.G6@28.7,32.1 ; v1(28.2,40.6) U1.R6@28.7,40.1 ; U1.H6@28.7,33.1 29.2,33.6 v1(31.2,33.6) ; U1.T6@28.7,41.1 v1(29.2,40.6) ; v1(29.2,34.6) U1.J7@29.7,34.1 ; v1(29.2,36.6) U1.M7@29.7,37.1 ; v1(29.2,38.6) U1.P7@29.7,39.1 ; U1.F7@29.7,31.1 v1(30.2,30.6) U1.F8@30.7,31.1 ; U1.K7@29.7,35.1 v1(30.2,34.6) ; U1.L7@29.7,36.1 v1(30.2,36.6) ; U1.N7@29.7,38.1 v1(30.2,38.6) ; U1.U7@29.7,42.1 v1(30.2,42.6) ; U1.U8@30.7,42.1 v1(31.2,42.6) ; v1(31.2,31.6) U1.G9@31.7,32.1 ; v1(31.2,41.6) U1.T9@31.7,41.1 ; U1.G10@32.7,32.1 v1(33.2,31.6) ; U1.T10@32.7,41.1 v1(33.2,40.6) ; v1(33.2,32.6) U1.G11@33.7,32.1 ; v1(33.2,41.6) U1.T11@33.7,41.1 ; v1(33.7,48.2) U1.AB11@33.7,47.1 ; v1(34.7,25.3) U1.A12@34.7,26.1 ; U1.G12@34.7,32.1 v1(35.2,32.6) v1@35.2,32.7 ; U1.T12@34.7,41.1 v1(35.2,40.6) U1.T13@35.7,41.1 ; v1(35.2,31.6) U1.G13@35.7,32.1 ; U1.G14@36.7,32.1 v1(37.2,32.6) ; U1.T14@36.7,41.1 v1(37.2,41.6) U1.U15@37.7,42.1 ; v1(37.2,31.6) U1.F15@37.7,31.1 ; v1(37.2,36.6) U1.N16@38.7,38.1 ; v1(37.2,39.6) v1(38.2,38.6) U1.P16@38.7,39.1 ; v1(38.2,30.6) U1.F16@38.7,31.1 ; v1(38.2,34.6) U1.K16@38.7,35.1 ; v1(38.2,36.6) U1.L16@38.7,36.1 ; v1(38.2,42.6) U1.U16@38.7,42.1 ; U1.J16@38.7,34.1 v1(39.2,34.6) ; U1.M16@38.7,37.1 v1(39.2,36.6) ; v1(39.2,40.6) U1.R17@39.7,40.1 ; U1.G17@39.7,32.1 v1(39.2,32.6) U1.H17@39.7,33.1 ; U1.T17@39.7,41.1 v1(40.2,40.6) ; U1.B22@44.7,27.1 44.95,27.1 v1(45.3,27.5) ; U1.M22@44.7,37.1 v1(45.45,37.1) ; U1.AA22@44.7,46.1 v1(45.2,46.6)
  Bottom Layer w0.3: U4.11@3.225,47.2 3.8,47.2 v1(4.5,47.1) ; v1(12.5,48) U4.33@14.375,48 ; v1(54.2,29.6) 54.6,29.6 U3.11@55.825,29.6 57.1,29.6 57.2,29.5 v1(58.4,29.5) ; U3.11@55.9,29.6 U3.11@55.925,29.6 ; v1(65.7,30.4) 65.8,30.4 U3.33@66.975,30.4
  Bottom Layer w0.4: HDR1.34@27.7,67.3 v1(27.7,69.6) v1(27.7,70.2) ; HDR1.40@30.1,67.3 30.1,69.1 v1(30.4,69.4) 30.6,69.6 v1(31.1,69.6) 31.1,69 v1(30.9,68.8) HDR1.42@30.9,67.3
  Bottom Layer w0.5: v1(51.1,19.2) v1(51.8,19.2) v1@51.7,19.2 ; v3(51.5,69.3) 51.7,69.1 v3@51.7,69 ; HDR2.94@51.7,16.5 v1(51.7,18.4) ; HDR1.94@51.7,67.3 v3@51.7,69 ; HDR2.96@52.5,16.5 v1(52.5,18.4) ; HDR1.96@52.5,67.3 v3@52.5,69 ; v3(52.7,69.3) 52.5,69.1 v3@52.5,69 ; v3@51.7,69 v3@52.5,69 ; v3@51.7,69 51.5,69 51.2,69 51,69.2 51,69.3 51,70.5 51,71 51.5,71 52.7,71 53.1,71 53.1,70.5 53.1,69.3 53.1,69.1 53,69 52.7,69 v3@52.5,69
  Bottom Layer w0.6: v1(51.1,19.2) 51,19.1 51.3,18.8 v1(51.7,18.4) 52.1,18.4 ; v1(51.8,19.2) 52.1,18.8 v1(52.5,18.4) 52.1,18.4 ; 52.1,18 52.1,18.4
  other v3: 51.5,70.5 52.7,70.5
VCCINT: C3.1 C4.1 C5.1 C6.1 C43.1 C44.1 C45.1 C46.1 C47.1 C48.1 C49.1 C50.1 C53.1 C54.1 C55.1 C59.1 C60.1 C61.1 C62.1 HDR1.93 HDR1.95 HDR2.93 HDR2.95 R8.1 TP11.1 U1.F6 U1.F17 U1.G7 U1.G8 U1.G15 U1.G16 U1.H7 U1.H16 U1.R7 U1.R16 U1.T7 U1.T8 U1.T15 U1.T16 U1.U6 U1.U17 | length 138.8
  Top Layer w0.2: C43.1@28.35,33.6 28.35,33.45 v1(29.2,32.6) ; v1(29.2,30.6) 29.2,30.75 C50.1@30.05,31.6 C50.1@30.1,31.6 ; 37.2,42.7 38.3,41.6 C44.1@38.35,41.6 ; C48.1@38.3,31.6 C48.1@38.35,31.6 38.35,31.548 38.35,31.5 38.35,31.45 v1(39.2,30.6)
  Top Layer w0.203: 22.227,25.902 22.227,25.873 22.8,25.3
  Top Layer w0.3: C59.1@27.6,35.7 27.6,34.35 C43.1@28.35,33.6 28.2,33.6 28.275,33.525 v1(29.2,32.6) ; C50.1@30.05,31.6 30.1,31.6 C50.1@30.2,31.6 ; C45.1@30.1,39.7 30.2,39.7 v1(31.2,39.7) ; C60.1@36.35,43.6 36.3,42.6 36.7,42.6 ; C48.1@38.35,31.5 39.2,30.65 v1(39.2,30.6) ; C48.1@38.35,31.6 38.35,31.548 v1@39.2,30.698 ; C44.1@38.4,41.8 v1(39.2,42.6)
  Top Layer w0.4: v1(29.2,30.6) 30.1,31.5 C50.1@30.1,31.6 ; v1(29.2,32.6) 29.2,32.45 C50.1@30.05,31.6 C50.1@30.1,31.6 ; C49.1@30,41.5 30,41.6 C49.1@30,41.65 ; C49.1@30,41.7 C49.1@30,41.65 ; C45.1@30.2,39.7 v1(30.2,40.6) C49.1@30.2,41.45 ; C49.1@30.2,41.6 C49.1@30.2,41.45 ; 31.1,30.7 C50.1@30.2,31.6 ; v1(31.2,32.6) C50.1@30.2,31.6 ; v1(31.2,39.7) v1(31.2,40.6) 31.05,40.6 C49.1@30.2,41.45 ; 37.3,30.7 38.2,31.6 v1(38.2,32.6) v1(38.2,33.6) C47.1@39.35,33.6 ; C44.1@38.2,41.3 v1(38.2,40.6) v1(38.2,39.6) C46.1@39.35,39.6 ; C44.1@38.2,41.6 37.2,42.6 36.3,42.6 32.2,42.6 31.4,43.4 30.15,43.4 29.8,43.4 29.4,43 29.4,42.25 C49.1@30,41.65 ; C49.1@30,41.65 C49.1@30.05,41.6 C49.1@30.2,41.45 ; C50.1@30.1,31.6 C50.1@30.2,31.6
  Top Layer w0.5: 31.1,30.7 33.2,30.7 37.3,30.7 ; C47.1@39.35,33.6 39.7,33.6 40.3,34.9 40.3,38.65 C46.1@39.35,39.6 ; v1(41.2,32.6) 46.2,32.6 C6.1@47.5,34.1
  MidLayer1 w0.2: 40.2,31.6 v1(41.2,32.6)
  MidLayer1 w0.3: 39.2,31.2 39.6,31.6 40.2,31.6
  MidLayer1 w0.4: v1(28.2,42.6) 30.2,41.3 v1(30.2,40.6) v1@30.3,40.6 ; v1(29.2,30.6) v1(29.2,32.6) 29.3,32.6 v1(30.2,32.6) v1(31.2,32.6) ; v1(38.2,33.6) v1(38.2,32.6) 38.2,32.3 39.2,31.3 39.2,31.2 v1(39.2,30.6) ; v1@30.3,40.6 31.2,40.6 v1(31.2,39.7) 30.75,40.15 v1@30.3,40.6
  MidLayer1 w0.5: v1@29.3,32.6 29.25,32.65 28.2,33.7 28.2,39 28.8,39.6 30.2,39.6 30.75,40.15 v1@31.2,40.6
  MidLayer2 w0.4: v1(29.2,30.6) v1(29.2,32.6) v1(30.2,32.6) v1(31.2,32.6) ; v1(30.2,40.6) v1(31.2,40.6) v1(31.2,39.7) ; v1(37.2,40.6) v1(38.2,40.6) 38.2,41.1 39.2,42.1 v1(39.2,42.6) ; v1(38.2,32.6) v1(38.2,33.6)
  MidLayer2 w0.6: v1(38.2,33.6) 40.5,33.6 41.2,32.9 v1(41.2,32.6)
  Bottom Layer w0.2: v1(28.2,42.6) U1.U6@28.7,42.1 ; U1.F6@28.7,31.1 v1(29.2,30.6) ; v1(29.2,32.6) U1.H7@29.7,33.1 ; U1.G7@29.7,32.1 v1(30.2,32.6) ; U1.R7@29.7,40.1 30.1,39.7 v1(31.2,39.7) ; U1.T7@29.7,41.1 v1(30.2,40.6) ; U1.G8@30.7,32.1 v1(31.2,32.6) ; U1.T8@30.7,41.1 v1(31.2,40.6) ; v1(37.2,33.6) 37.7,33.1 ; v1(37.2,40.6) 37.45,40.85 U1.T15@37.7,41.1 ; U1.G15@37.7,32.1 v1(38.2,32.6) ; v1(38.2,39.6) U1.R16@38.7,40.1 ; v1(38.2,40.6) U1.T16@38.7,41.1 ; U1.G16@38.7,32.1 v1(38.2,32.6) ; U1.H16@38.7,33.1 v1(38.2,33.6) 37.7,33.1 ; v1(39.2,30.6) U1.F17@39.7,31.1 ; v1(39.2,42.6) U1.U17@39.7,42.1 ; 37.7,33.1 v1(38.2,32.6)
  Bottom Layer w0.3: v1(50.6,55.5) 50.6,56.1 v2(51.7,57.2) HDR1.93@51.7,60.5 ; v1(51.3,55.5) 52.5,56.7 v2(52.5,58.4) HDR1.95@52.5,60.5
  Bottom Layer w0.4: HDR2.93@51.7,9.7 51.7,7.7 TP11.1@52.9,6.5 52.9,7.4 52.5,7.8 v1(52.5,8) HDR2.95@52.5,9.7
VDRIVE: HDR1.20 U1.P4 | length 50
  MidLayer1 w0.127: 24.7,38.1 25.7,38.1
  MidLayer1 w0.2: v1(22.1,73) 21,71.9 21,64.9 15.7,59.6 15.7,58.5 15.1,57.9 15.1,56.4 18.1,53.4 18.1,44.5 24.5,38.1 24.7,38.1 ; 25.7,38.1 v1(26.2,38.6)
  Bottom Layer w0.2: HDR1.20@22.1,67.3 v1(22.1,73) ; v1(26.2,38.6) U1.P4@26.7,39.1
VREF: HDR1.91 R8.2 R9.1 | length 18.1
  Top Layer w0.3: R9.1@54.45,53 55.4,53 55.8,53.4 v1(55.8,55.8) R8.2@54.5,55.8
  Bottom Layer w0.2: HDR1.91@50.9,60.5 50.9,57.5 49.8,56.4 49.8,55.1 50.7,54.2 54.2,54.2 v1(55.8,55.8)
pads on no net: HDR1.MH1 HDR1.MH2 HDR1.MH3 HDR1.MH4 HDR1.MH5 HDR1.MH6 HDR2.MH1 HDR2.MH2 HDR2.MH3 HDR2.MH4 HDR2.MH5 HDR2.MH6 U1.A11 U1.A20 U1.AA11 U1.AB19 U1.AB21 U1.C11 U1.D11 U1.D12 U1.E9 U1.E11 U1.E18 U1.F5 U1.F9 U1.F10 U1.F11 U1.F12 U1.F13 U1.G5 U1.G18 U1.G20 U1.H3 U1.H5 U1.H18 U1.H19 U1.J3 U1.J4 U1.J5 U1.J6 U1.J17 U1.J18 U1.J19 U1.K5 U1.K6 U1.K17 U1.L5 U1.L6 U1.L17 U1.M5 U1.M6 U1.M17 U1.N5 U1.N6 U1.N17 U1.P5 U1.P6 U1.P17 U1.P18 U1.R5 U1.T5 U1.U5 U1.U9 U1.U10 U1.U12 U1.U13 U1.U14 U1.V5 U1.V6 U1.V7 U1.V8 U1.V10 U1.V12 U1.V13 U1.V14 U1.V15 U1.V16 U1.V17 U1.W5 U1.W8 U1.W11 U1.W13 U1.W16 U1.W17 U1.W18 U1.Y4 U1.Y5 U1.Y11 U1.Y13 U1.Y16 U1.Y17 U1.Y18 U2.1 U2.5 U2.9 U2.13 U2.16 U5.1
copper on no net: | length 8.2
  Bottom Layer w1: 55.9,45.9 55.9,54.1

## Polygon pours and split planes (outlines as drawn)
VCCINT on Top Layer "Top Layer-VCCINT" (solid, remove dead copper, pour order 1000): -3.2,83.8 72.8,83.8 72.8,-7.3 -5.3,-7.3 -5.3,84 -2.9,84
GND on MidLayer1 "MidLayer1-GND" (solid, remove dead copper, pour order 1001): -6.9,83.4 72.5,83.4 72.5,-3.3 -3.5,-3.3 -3.5,83.3
VCCINT on MidLayer2 "MidLayer2-VCCINT" (solid, remove dead copper, pour order 1002): -4.2,83 72.1,83 72.1,-5.2 -2.5,-5.2 -2.5,83
VCC on InternalPlane1 (split plane): 36.228,79.789 37.955,79.759 39.683,79.709 41.409,79.639 43.135,79.55 44.859,79.44 46.582,79.31 48.303,79.161 50.023,78.991 51.74,78.802 53.455,78.593 55.168,78.364 56.878,78.116 58.585,77.847 60.289,77.559 61.989,77.252 63.685,76.924 65.378,76.578 67.067,76.211 67.798,76.044 67.798,1.202 1.202,1.202 1.203,76.044 1.933,76.211 3.622,76.578 5.315,76.924 7.011,77.252 8.711,77.559 10.415,77.847 12.122,78.116 13.832,78.364 15.545,78.593 17.26,78.802 18.977,78.991 20.697,79.161 22.418,79.31 24.141,79.44 25.865,79.55 27.591,79.639 29.317,79.709 31.045,79.759 32.772,79.789 34.5,79.799
GND on InternalPlane2 (split plane): 36.228,79.789 37.955,79.759 39.683,79.709 41.409,79.639 43.135,79.55 44.859,79.44 46.582,79.31 48.303,79.161 50.023,78.991 51.74,78.802 53.455,78.593 55.168,78.364 56.878,78.116 58.585,77.847 60.289,77.559 61.989,77.252 63.685,76.924 65.378,76.578 67.067,76.211 67.798,76.044 67.798,1.202 1.202,1.202 1.203,76.044 1.933,76.211 3.622,76.578 5.315,76.924 7.011,77.252 8.711,77.559 10.415,77.847 12.122,78.116 13.832,78.364 15.545,78.593 17.26,78.802 18.977,78.991 20.697,79.161 22.418,79.31 24.141,79.44 25.865,79.55 27.591,79.639 29.317,79.709 31.045,79.759 32.772,79.789 34.5,79.799

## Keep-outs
Keep-Out Layer:
  lines w1.3: 0.001,77 cw(c34.5,-69.801) 68.999,77 ; 0.001,77 cw(c34.5,-69.801) 68.999,77 ; 0.001,77 cw(c34.5,-69.801) 68.999,77 ; 0.001,77 0,76.999 0,0 69,0 69,76.999 68.999,77

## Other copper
Top Layer:
  rectangle net GND: 53.1,17.7 54.4,18.9
Bottom Layer:
  rectangle net VBATT: 59,42.5 66.3,44.4
  rectangle net VBATT: 58.9,55.7 66.2,57.6
  rectangle net VCC: 30.3,68.6 31.1,69.6
  rectangle net GND: 28.5,69.3 29.6,70.4
  rectangle net VCC: 50.9,69.2 53.3,71.1

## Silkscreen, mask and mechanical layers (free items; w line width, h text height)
Top Overlay:
  circle w0.127: c65,4 r2.5
  circle w0.127: c4,34 r2.5
  circle w0.127: c60.8,13.1 r2.5
  circle w0.127: c65,73 r2.5
  lines w0.08: 1.1,36.6 1.4,30.9 ; 3.1,57.5 3.82,57.52 ; 5.95,28 6.5,27.7 ; 10.1,57.6 10.7,57.5 ; 13.6,20 13.8,19.3 ; 14.2,16.4 15.32,17.32 ; 14.3,25.8 15.8,24.4 ; 15.1,1.5 17.6,1.5 ; 19.7,49.1 20.5,48.4 ; 20.7,25.7 20.8,26 ; 21.8,56.1 22.2,55.6 ; 22.6,43.3 26.7,43.1 27.8,42.3 ; 22.9,28.8 23.22,29.12 ; 24.4,48 24.9,46.5 ; 24.5,38.4 28.7,38.2 ; 24.7,24.35 24.9,25.1 ; 24.9,7.9 24.9,8.4 ; 24.9,36 26.6,36.4 ; 25.2,35 28.7,35.1 ; 25.9,45.1 27.1,44.9 27.8,44.3 ; 26.2,1.6 26.8,1.6 ; 26.6,40.2 27.7,39.9 ; 26.713,33.22 27.6,33.5 ; 27.4,30.9 27.9,31 ; 28,7.3 28.2,8.6 ; 29.3,42.6 29.3,43.2 ; 30.5,20.8 31.42,20.12 ; 30.7,56.1 31.3,56.5 ; 31.5,27.2 31.9,31.1 ; 32,8.6 32.3,7.3 ; 32,48.5 32.02,47.78 ; 33.7,27.4 33.9,28.4 ; 34.3,31.2 35.5,28.4 ; 35.7,42.1 35.7,44.6 ; 36.6,31 36.8,31.3 ; 37.7,75.8 39.9,73.8 ; 38.6,44.3 38.9,44.6 38.9,45.1 ; 39.6,43.1 39.7,42.6 ; 39.7,35.2 43.72,35.12 ; 39.8,37.9 43.4,38.1 ; 40.7,31.6 41.92,32.12 ; 41.7,33.9 43.6,34.1 ; 41.8,40 43.5,40.1 ; 41.9,49.3 42.65,48.75 ; 42,70.5 42.02,68.48 ; 43,2.5 44.82,1.82 ; 44.9,74.7 44.9,75.1 ; 45.8,71.6 46.02,71.78 ; 47.92,9.12 48.1,6.8 ; 49,36.6 49.82,36.62 ; 49.8,44.7 50.6,44.5 ; 52.5,59.3 53.4,58.5 ; 54,6.8 54.5,7.1 ; 55.3,55.2 56.42,55.12 ; 56.3,77.1 56.9,77 ; 64.6,41.9 65.8,41.3
  text "+" at 64.6,55.9 h1.52
  text "-" at 59.5,49.3 h1.52
  text "+" at 62,45 h1.52
Bottom Overlay:
  drawing of 860 lines, arcs and shapes, not listed
  text "REV 1.10" at 46.6,76.4 h1.3
  text "NBP7" at 53.9,76.4 h1.3
  text "+" at 4.9,75.5 h1.52
  text "-" at 10.8,75.4 h1.52
  text "1" at 13.97,58.42 h1
  text "1" at 14.224,7.62 h1
PCB Boundary:
  lines w0.25: 0.001,77 cw(c34.5,-69.801) 69,77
